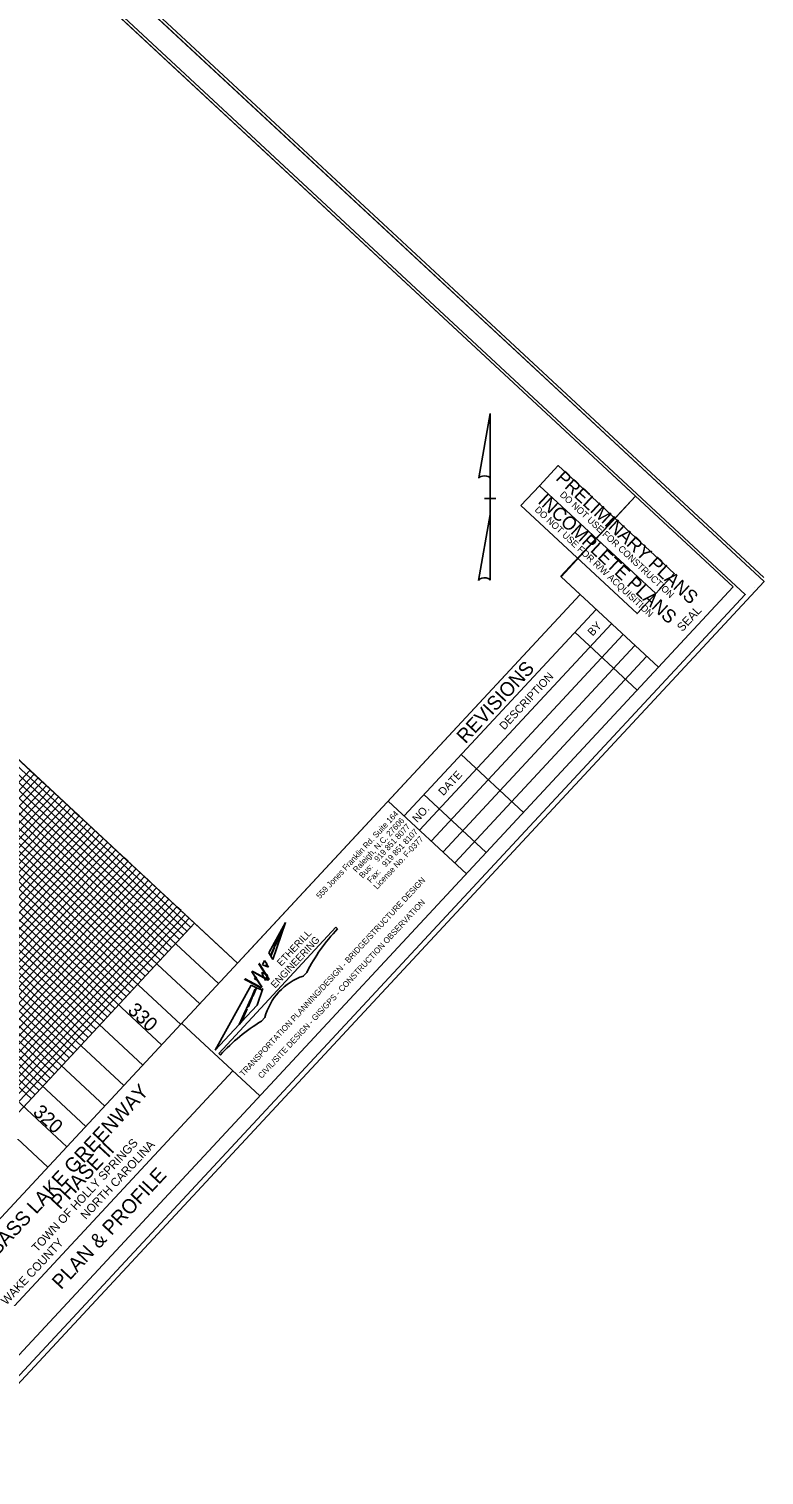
# Model space of a CAD drawing. Extents: x 2057696 to 2061410, y 685900 to 689434.
# Drawn here: x 2058752 to 2059279, y 687875 to 688913 of the extents above; entities that cross this region are included whole.
import ezdxf

# ---------------------------------------------------------------- set-up
doc = ezdxf.new("R2010")
doc.units = 0
for name, color, linetype in [('Default', 7, 'Continuous'), ('Exist Vertical Profile Vertical Axis Label', 7, 'Continuous'), ('Prop Horizontal Alignment Tick Small', 7, 'Continuous'), ('Prop PFL Text', 7, 'Continuous'), ('Prop Roadway Bridge', 7, 'Continuous'), ('Prop SS Fill Line', 7, 'Continuous'), ('Prop Vertical Profile Curve Label', 7, 'Continuous'), ('Sheet Border Standard 30in CELL', 7, 'Continuous'), ('Sheet Cutting Line CELL', 7, 'Continuous'), ('Sheet Plan CELL', 7, 'Continuous'), ('Sheet Plot Border Inside CELL', 7, 'Continuous')]:
    doc.layers.add(name, color=color, linetype=linetype)

# ---------------------------------------------------------------- blocks, each defined once
blk = doc.blocks.new('North Arrow for Plan Sheets')
at = {"layer": 'Prop PFL Text'}
for p, q in [((-6.32, 11.16), (-0.07, 46.48)), ((-0.03, 46.48), (-0.07, 46.48)), ((-0.07, 46.48), (-0.03, 46.48)), ((-0.03, 46.48), (-0.03, 10.06)), ((-6.3, 11.15), (-6.32, 11.16)), ((-0.03, -8.84), (-0.03, 11.13)), ((-0.03, 10.06), (-0.03, 11.09)), ((-0.03, 11.09), (-0.02, 11.08)), ((-3.08, 0), (-3.12, 0)), ((-0.38, 0), (-3.08, 0)), ((-3.04, 0), (3.05, 0)), ((-0.03, -8.84), (-6.4, -44.84)), ((0, -44.69), (-0.03, -8.84)), ((-6.4, -44.84), (-6.39, -44.95)), ((-0.01, -44.7), (0, -44.69))]:
    blk.add_line(p, q, dxfattribs=at)
blk.add_lwpolyline([(-0.03, 46.48), (-0.07, 46.48)], dxfattribs=at)
for centre, start_param, end_param in [((-3.17, 10.79), 0.216388, 2.908219), ((-3.17, -44.97), 0.201328, 3.141593)]:
    blk.add_ellipse(centre, major_axis=(3.22, -0.02), ratio=0.461098, start_param=start_param, end_param=end_param, dxfattribs=at)

msp = doc.modelspace()

# ---------------------------------------------------------------- linework, layer by layer
at = {"layer": 'Default'}
for p, q in [((2059279.2, 688516.6), (2058292.7, 689433.5)), ((2059279, 688519.5), (2058353.1, 689380.2)), ((2059257, 688512.7), (2058378, 689329.7)), ((2059186.8, 688577.9), (2059133.2, 688520.2)), ((2059133.6, 688519.9), (2059203.4, 688455)), ((2059147.2, 688507.2), (2058628.8, 687949.4)), ((2059257, 688512.7), (2058684.9, 687897.2)), ((2059020.9, 688348.3), (2059158.6, 688496.5)), ((2059032, 688338.1), (2059169.7, 688486.3)), ((2059040.4, 688330.3), (2059178.1, 688478.5)), ((2059143.4, 688480.2), (2059188, 688438.6)), ((2059048.8, 688322.5), (2059186.5, 688470.7)), ((2059057.2, 688314.6), (2059194.9, 688462.8)), ((2059061.8, 688392.4), (2059106.5, 688350.8)), ((2059009.5, 688359), (2059065.6, 688306.8)), ((2059035.1, 688363.6), (2059079.6, 688322.2)), ((2058781.6, 688353.8), (2058522.9, 688075.5)), ((2058854.9, 688285.7), (2058596.2, 688007.4)), ((2058887.8, 688177.7), (2058971.9, 688268.3)), ((2058935.8, 688271.7), (2058923.8, 688250.1)), ((2058935.8, 688271.7), (2058926.6, 688245.1)), ((2058931.5, 688262.5), (2058933.1, 688265.9)), ((2058931.7, 688262.7), (2058933.2, 688266)), ((2058933.4, 688266.4), (2058933.1, 688265.9)), ((2058933.1, 688265.9), (2058933.2, 688266)), ((2058933.4, 688266.4), (2058934.5, 688268.9)), ((2058933.5, 688266.6), (2058933.4, 688266.4)), ((2058933.5, 688266.6), (2058934.6, 688268.9)), ((2058934.6, 688269.3), (2058934.5, 688268.9)), ((2058934.5, 688268.9), (2058934.6, 688268.9)), ((2058934.6, 688269.3), (2058935.3, 688270.8)), ((2058934.7, 688269.4), (2058934.6, 688269.3)), ((2058934.7, 688269.4), (2058935.4, 688270.8)), ((2058935.3, 688270.8), (2058935.4, 688270.8)), ((2058935.4, 688270.8), (2058935.3, 688270.8)), ((2058935.4, 688270.8), (2058935.8, 688271.7)), ((2058935.4, 688270.9), (2058935.8, 688271.7)), ((2058935.4, 688270.9), (2058935.8, 688271.7)), ((2058935.4, 688270.9), (2058935.4, 688270.8)), ((2058971.9, 688268.3), (2058973.1, 688267.2)), ((2058927.9, 688254.5), (2058927.4, 688253.4)), ((2058927.9, 688254.5), (2058931.2, 688261.7)), ((2058928.4, 688255), (2058927.9, 688254.5)), ((2058928.4, 688255), (2058931.5, 688261.9)), ((2058931.5, 688262.5), (2058931.2, 688261.7)), ((2058931.2, 688261.7), (2058931.5, 688261.9)), ((2058931.7, 688262.7), (2058931.5, 688262.5)), ((2058919.1, 688241.4), (2058920.7, 688244.5)), ((2058922.2, 688242), (2058920.7, 688244.5)), ((2058923.8, 688250.1), (2058924.9, 688248)), ((2058924.9, 688248), (2058927.4, 688253.4)), ((2058925.1, 688247.7), (2058924.9, 688248)), ((2058925.1, 688247.7), (2058927.9, 688253.9)), ((2058926.6, 688245.1), (2058925.1, 688247.7)), ((2058927.4, 688253.4), (2058927.9, 688253.9)), ((2058918.6, 688235.8), (2058919.3, 688235.6)), ((2058919, 688235), (2058918.6, 688235.8)), ((2058919.3, 688235.6), (2058919, 688235)), ((2058919, 688235), (2058919.3, 688234.5)), ((2058919.1, 688241.4), (2058921.5, 688240.4)), ((2058919.3, 688235.6), (2058919.6, 688235.4)), ((2058919.3, 688234.5), (2058919.6, 688235.4)), ((2058921.4, 688230.2), (2058919.3, 688234.5)), ((2058919.6, 688235.4), (2058922.7, 688234.1)), ((2058922.7, 688234.1), (2058921.4, 688230.2)), ((2058921.5, 688240.4), (2058922.2, 688242)), ((2058921.9, 688240.3), (2058921.5, 688240.4)), ((2058922.4, 688241.7), (2058921.9, 688240.3)), ((2058921.9, 688240.3), (2058923.6, 688239.7)), ((2058922.4, 688241.7), (2058922.2, 688242)), ((2058923.6, 688239.7), (2058922.4, 688241.7)), ((2058951, 688235.9), (2058948.6, 688233.4)), ((2058885.3, 688180.1), (2058911, 688226.8)), ((2058911, 688226.8), (2058915, 688224.9)), ((2058911.2, 688217.7), (2058913.8, 688223.6)), ((2058912.6, 688219.2), (2058915, 688224.9)), ((2058912.6, 688219.2), (2058915, 688224.9)), ((2058913.5, 688231.4), (2058914.3, 688232.8)), ((2058915.4, 688230.4), (2058913.5, 688231.4)), ((2058915, 688224.9), (2058913.8, 688223.6)), ((2058914.3, 688232.8), (2058915.4, 688230.4)), ((2058915, 688224.9), (2058918.4, 688223.3)), ((2058919.4, 688224.4), (2058915.3, 688212.4)), ((2058918.4, 688223.3), (2058919.4, 688224.4)), ((2058907.6, 688209.9), (2058910.5, 688216.4)), ((2058909.1, 688211.5), (2058911.8, 688217.8)), ((2058910.5, 688216.4), (2058911.8, 688217.8)), ((2058911.2, 688217.7), (2058910.5, 688216.4)), ((2058912.6, 688219.2), (2058911.2, 688217.7)), ((2058902.4, 688198.5), (2058906.7, 688208.1)), ((2058915.3, 688212.4), (2058904.2, 688200.5)), ((2058904.2, 688200.5), (2058908.3, 688209.8)), ((2058907.6, 688209.9), (2058906.7, 688208.1)), ((2058906.7, 688208.1), (2058908.3, 688209.8)), ((2058908.3, 688209.8), (2058906.7, 688208.1)), ((2058906.7, 688208.1), (2058908.3, 688209.8)), ((2058909.1, 688211.5), (2058907.6, 688209.9)), ((2058920.9, 688203.6), (2058918.5, 688201)), ((2058861.1, 688199.4), (2058917.3, 688147.2)), ((2058902.4, 688198.5), (2058885.3, 688180.1)), ((2058902.4, 688198.5), (2058904.2, 688200.5)), ((2058889, 688176.6), (2058887.8, 688177.7)), ((2058724.1, 687978.2), (2058897.9, 688165.2))]:
    msp.add_line(p, q, dxfattribs=at)
for points in [[(2057696.3, 688791.9), (2058682.8, 687875), (2059279.2, 688516.6), (2058292.7, 689433.5)], [(2057714.8, 688796.5), (2058691.1, 687889.2), (2059265.7, 688507.4), (2058289.4, 689414.7)]]:
    msp.add_lwpolyline(points, close=True, dxfattribs=at)
for centre, major_axis, start_param, end_param in [((2059057.7, 688185.5), (-83.6, -89.9), 4.694176, 5.007823), ((2058960.2, 688194.8), (-28.3, -30.5), 4.202115, 5.222667), ((2058979.1, 688095), (-86.4, -93), 4.422177, 4.725362)]:
    msp.add_ellipse(centre, major_axis=major_axis, ratio=0.957702, start_param=start_param, end_param=end_param, dxfattribs=at)
at = {"layer": 'Exist Vertical Profile Vertical Axis Label'}
for points in [[(2058496.6, 688100), (2058755.3, 688378.3), (2058758.2, 688375.6), (2058499.5, 688097.3)], [(2058502.4, 688094.5), (2058761.1, 688372.9), (2058764.1, 688370.2), (2058505.4, 688091.8)], [(2058511.2, 688086.4), (2058769.9, 688364.7), (2058772.8, 688362), (2058514.1, 688083.6)], [(2058517.1, 688080.9), (2058775.8, 688359.3), (2058778.7, 688356.5), (2058520, 688078.2)], [(2058525.9, 688072.8), (2058784.6, 688351.1), (2058787.5, 688348.4), (2058528.8, 688070)], [(2058531.7, 688067.3), (2058790.4, 688345.6), (2058793.4, 688342.9), (2058534.6, 688064.6)], [(2058540.5, 688059.1), (2058799.2, 688337.5), (2058802.1, 688334.7), (2058543.4, 688056.4)], [(2058546.4, 688053.7), (2058805.1, 688332), (2058808, 688329.3), (2058549.3, 688051)], [(2058555.2, 688045.5), (2058813.9, 688323.9), (2058816.8, 688321.1), (2058558.1, 688042.8)], [(2058561, 688040.1), (2058819.7, 688318.4), (2058822.7, 688315.7), (2058563.9, 688037.4)], [(2058569.8, 688031.9), (2058828.5, 688310.2), (2058831.4, 688307.5), (2058572.7, 688029.2)], [(2058575.7, 688026.5), (2058834.4, 688304.8), (2058837.3, 688302.1), (2058578.6, 688023.7)], [(2058584.5, 688018.3), (2058843.2, 688296.6), (2058846.1, 688293.9), (2058587.4, 688015.6)], [(2058590.3, 688012.8), (2058849, 688291.2), (2058852, 688288.5), (2058593.2, 688010.1)], [(2058599.1, 688004.7), (2058857.8, 688283), (2058860.7, 688280.3), (2058602, 688001.9)], [(2058605, 687999.2), (2058863.7, 688277.6), (2058866.6, 688274.8), (2058607.9, 687996.5)]]:
    msp.add_lwpolyline(points, dxfattribs=at)
at = {"layer": 'Prop Horizontal Alignment Tick Small'}
msp.add_line((2059272.2, 688512.2), (2059272.2, 688512.2), dxfattribs=at)
at = {"layer": 'Prop Roadway Bridge'}
msp.add_lwpolyline([(2059117.9, 688585.4), (2059131.3, 688599.8), (2059214.7, 688522.3), (2059201.4, 688507.9)], close=True, dxfattribs=at)
at = {"layer": 'Prop SS Fill Line'}
msp.add_lwpolyline([(2059104.6, 688571.1), (2059117.9, 688585.4), (2059201.4, 688507.9), (2059188, 688493.6)], close=True, dxfattribs=at)
at = {"layer": 'Prop Vertical Profile Curve Label'}
for points in [[(2058078.5, 689007.4), (2058901.3, 688242.6), (2059147.2, 688507.2), (2059133.6, 688519.9), (2059186.8, 688577.9), (2058378, 689329.7)], [(2057849.1, 688701.8), (2058611.6, 687993), (2058870.3, 688271.4), (2058107.8, 688980.2)]]:
    msp.add_lwpolyline(points, close=True, dxfattribs=at)
at = {"layer": 'Sheet Border Standard 30in CELL'}
for p, q in [((2058887.7, 688227.9), (2058064.9, 688992.7)), ((2058860.5, 688198.6), (2058037.6, 688963.4)), ((2058833.2, 688169.3), (2058010.4, 688934.1)), ((2058806, 688140), (2057983.2, 688904.8)), ((2058778.8, 688110.7), (2057955.9, 688875.5)), ((2058508.3, 688089.1), (2058767, 688367.4)), ((2058796.3, 688340.2), (2058537.6, 688061.9)), ((2058566.9, 688034.6), (2058825.6, 688313)), ((2058854.9, 688285.7), (2058596.2, 688007.4))]:
    msp.add_line(p, q, dxfattribs=at)
for points in [[(2058493.6, 688102.7), (2058752.3, 688381), (2058781.6, 688353.8), (2058522.9, 688075.5)], [(2058552.2, 688048.2), (2058810.9, 688326.6), (2058840.2, 688299.3), (2058581.5, 688021)]]:
    msp.add_lwpolyline(points, dxfattribs=at)
at = {"layer": 'Sheet Cutting Line CELL'}
for p, q in [((2058901.3, 688242.6), (2058078.5, 689007.4)), ((2058874.1, 688213.3), (2058051.2, 688978.1)), ((2058846.8, 688184), (2058024, 688948.8)), ((2058819.6, 688154.7), (2057996.8, 688919.5)), ((2058792.4, 688125.4), (2057969.5, 688890.2)), ((2058765.1, 688096.1), (2057942.3, 688860.9)), ((2058611.6, 687993), (2058870.3, 688271.4))]:
    msp.add_line(p, q, dxfattribs=at)
at = {"layer": 'Sheet Plot Border Inside CELL'}
for p, q in [((2058862.2, 688262.6), (2058099.6, 688971.4)), ((2058864.9, 688265.5), (2058102.3, 688974.3)), ((2058867.6, 688268.5), (2058105, 688977.2)), ((2058854, 688253.8), (2058091.4, 688962.6)), ((2058859.4, 688259.7), (2058096.9, 688968.4)), ((2058845.8, 688245), (2058083.3, 688953.8)), ((2058848.5, 688247.9), (2058086, 688956.7)), ((2058851.3, 688250.9), (2058088.7, 688959.6)), ((2058834.9, 688233.3), (2058072.4, 688942.1)), ((2058837.6, 688236.2), (2058075.1, 688945)), ((2058840.4, 688239.2), (2058077.8, 688947.9)), ((2058824, 688221.6), (2058061.5, 688930.3)), ((2058826.7, 688224.5), (2058064.2, 688933.3)), ((2058832.2, 688230.4), (2058069.6, 688939.1)), ((2058813.1, 688209.9), (2058050.6, 688918.6)), ((2058818.6, 688215.7), (2058056, 688924.5)), ((2058821.3, 688218.6), (2058058.8, 688927.4)), ((2058805, 688201.1), (2058042.4, 688909.8)), ((2058807.7, 688204), (2058045.1, 688912.8)), ((2058810.4, 688206.9), (2058047.9, 688915.7)), ((2058794.1, 688189.3), (2058031.5, 688898.1)), ((2058796.8, 688192.3), (2058034.2, 688901)), ((2058799.5, 688195.2), (2058037, 688904)), ((2058785.9, 688180.6), (2058023.3, 688889.3)), ((2058791.3, 688186.4), (2058028.8, 688895.2)), ((2058777.7, 688171.8), (2058015.2, 688880.5)), ((2058780.5, 688174.7), (2058017.9, 688883.5)), ((2058783.2, 688177.6), (2058020.6, 688886.4)), ((2058766.8, 688160), (2058004.3, 688868.8)), ((2058769.6, 688163), (2058007, 688871.7)), ((2058772.3, 688165.9), (2058009.7, 688874.7)), ((2058755.9, 688148.3), (2057993.4, 688857.1)), ((2058758.7, 688151.3), (2057996.1, 688860)), ((2058764.1, 688157.1), (2058001.6, 688865.9)), ((2058753.2, 688145.4), (2057990.7, 688854.2))]:
    msp.add_line(p, q, dxfattribs=at)

# ---------------------------------------------------------------- block references
at = {"layer": 'Prop PFL Text', "xscale": 1.3123333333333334, "yscale": 1.3123333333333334}
msp.add_blockref('North Arrow for Plan Sheets', (2059082.7, 688576.3), dxfattribs=at)

# ---------------------------------------------------------------- texts
at = {"layer": 'Default'}
for s, height, p in [('SEAL', 6.13, (2059220.5, 688480.2)), ('BY', 5.75, (2059156.1, 688477)), ('REVISIONS', 10.11, (2059064.9, 688399.7)), ('DESCRIPTION', 5.746, (2059092.8, 688409.6)), ('DATE', 5.75, (2059049, 688362.4)), ('559 Jones Franklin Rd. Suite 164', 4.214, (2058960.4, 688288.5)), ('NO.', 5.75, (2059030.3, 688343.1)), ('Raleigh, N.C. 27606', 4.229, (2058986.7, 688307.3)), ('Bus:   919 851 8077', 4.229, (2058991.1, 688303.2)), ('Fax:   919 851 8107', 4.229, (2058996.9, 688299.8)), ('License No. F-0377', 4.229, (2059001.5, 688295.2)), ('TRANSPORTATION PLANNING/DESIGN - BRIDGE/STRUCTURE DESIGN', 4.229, (2058905.5, 688161)), ('CIVIL/SITE DESIGN - GIS/GPS - CONSTRUCTION OBSERVATION', 4.229, (2058918.6, 688159.4)), ('ETHERILL', 5.07, (2058932.7, 688240)), ('ENGINEERING', 5.074, (2058928.3, 688224.2)), ('W', 13.5, (2058915.5, 688221.4)), ('WAKE COUNTY          NORTH CAROLINA', 6.129, (2058735.4, 687996.7)), ('TOWN OF HOLLY SPRINGS', 6.129, (2058757.4, 688034.7))]:
    msp.add_text(s, height=height, rotation=47.0934, dxfattribs=at).set_placement(p)
at = {"layer": 'Prop Roadway Bridge'}
for s, height, p in [('PRELIMINARY PLANS', 9.6, (2059129.1, 688590)), ('DO NOT USE FOR CONSTRUCTION', 4.8, (2059132.2, 688578.4))]:
    msp.add_text(s, height=height, rotation=317.0934, dxfattribs=at).set_placement(p)
at = {"layer": 'Prop SS Fill Line'}
for s, height, p in [('INCOMPLETE PLANS', 9.6, (2059116.3, 688573.5)), ('DO NOT USE FOR R/W ACQUISITION', 4.8, (2059114.2, 688567.6))]:
    msp.add_text(s, height=height, rotation=317.0934, dxfattribs=at).set_placement(p)
at = {"layer": 'Sheet Cutting Line CELL'}
for s, height, p in [('BASS LAKE GREENWAY', 10.342, (2058728.9, 688032)), ('PHASE II', 10.34, (2058773.8, 688065.1)), ('PLAN & PROFILE', 10.342, (2058774.6, 688007.7))]:
    msp.add_text(s, height=height, rotation=47.0934, dxfattribs=at).set_placement(p)
at = {"layer": 'Sheet Plan CELL'}
for s, p in [('330', (2058821.8, 688207.9)), ('320', (2058753.8, 688134.7))]:
    msp.add_text(s, height=10, rotation=317.0934, dxfattribs=at).set_placement(p)

doc.saveas('drawing.dxf')
